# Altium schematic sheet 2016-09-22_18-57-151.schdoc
size 346 x 128 mm; SheetNumber: 1; SheetTotal: 1
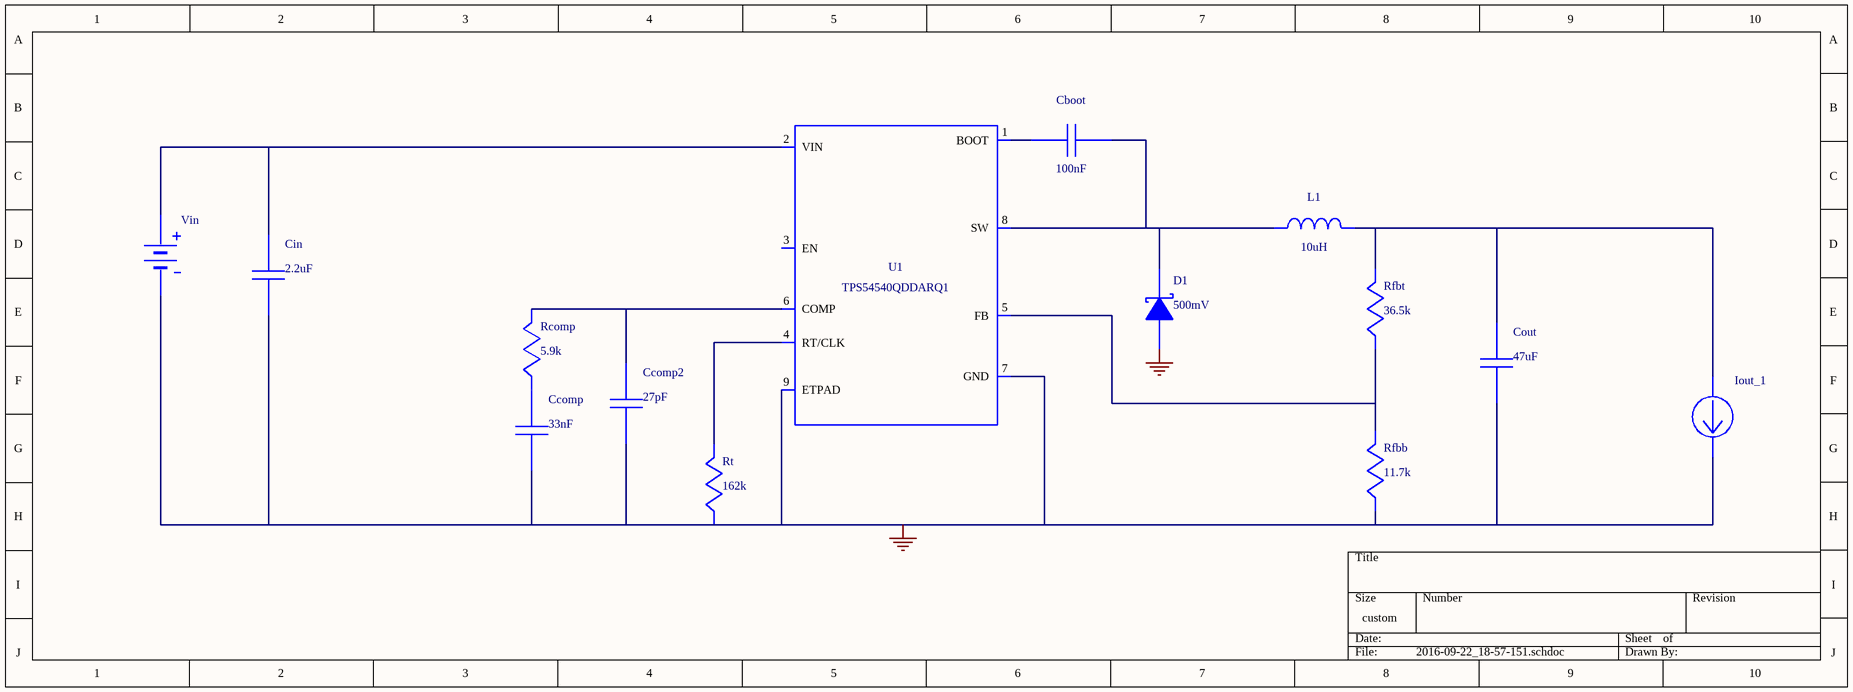
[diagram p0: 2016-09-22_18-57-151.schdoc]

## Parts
Cboot  value 100nF  (hidden comment: GRM155R61A104KA01D)
Ccomp  value 33nF  (hidden comment: GRM033R60J333KE01D)
Ccomp2  value 27pF  (hidden comment: C0805C270K5GACTU)
Cin  value 2.2uF  (hidden comment: GRM31CR71H225KA88L)
Cout  value 47uF  (hidden comment: GRM31CC80J476KE18L)
D1  value 500mV  (hidden comment: B340A-13-F)
Iout_1  WB_CURRENT_LOAD  (value not drawn)
L1  value 10uH  (hidden comment: SRN8040-100M)
Rcomp  value 5.9k  (hidden comment: CRCW04025K90FKED)
Rfbb  value 11.7k  (hidden comment: RT0805BRD0711K7L)
Rfbt  value 36.5k  (hidden comment: CRCW040236K5FKED)
Rt  value 162k  (hidden comment: CRCW0402162KFKED)
U1  TPS54540QDDARQ1
Vin  WB_BATTERY  (value not drawn)

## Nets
0: Ccomp.2 Ccomp2.2 Cin.2 Cout.2 D1.2(A) Iout_1.2(-) Rfbb.2 Rt.2 U1.7(GND) U1.9(ETPAD) Vin.2(-)
NetCboot_1: Cboot.1 U1.1(BOOT)
NetCboot_2: Cboot.2 D1.1(K) L1.1 U1.8(SW)
NetCcomp2_1: Ccomp2.1 Rcomp.1 U1.6(COMP)
NetCcomp_1: Ccomp.1 Rcomp.2
NetCin_1: Cin.1 U1.2(VIN) Vin.1(+)
NetCout_1: Cout.1 Iout_1.1(+) L1.2 Rfbt.1
NetRfbb_1: Rfbb.1 Rfbt.2 U1.5(FB)
NetRt_1: Rt.1 U1.4(RT/CLK)

Not connected (* = marked no-connect by the designer): U1 3(EN)

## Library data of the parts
Cboot = GRM155R61A104KA01D: GRM155R61A104KA0; Manufacturer Name: MuRata
Ccomp = GRM033R60J333KE01D: GRM033R60J333KE0; Manufacturer Name: MuRata
Ccomp2 = C0805C270K5GACTU: Manufacturer Name: Kemet
Cin = GRM31CR71H225KA88L: GRM31CR71H225KA8; Manufacturer Name: MuRata
Cout = GRM31CC80J476KE18L: GRM31CC80J476KE1; Manufacturer Name: MuRata
D1 = B340A-13-F: Manufacturer Name: Diodes Inc.
L1 = SRN8040-100M: Manufacturer Name: Bourns
Rcomp = CRCW04025K90FKED: Manufacturer Name: Vishay-Dale
Rfbb = RT0805BRD0711K7L: Manufacturer Name: Yageo America
Rfbt = CRCW040236K5FKED: Manufacturer Name: Vishay-Dale
Rt = CRCW0402162KFKED: Manufacturer Name: Vishay-Dale
U1 = TPS54540QDDARQ1: Manufacturer Name: Texas Instruments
